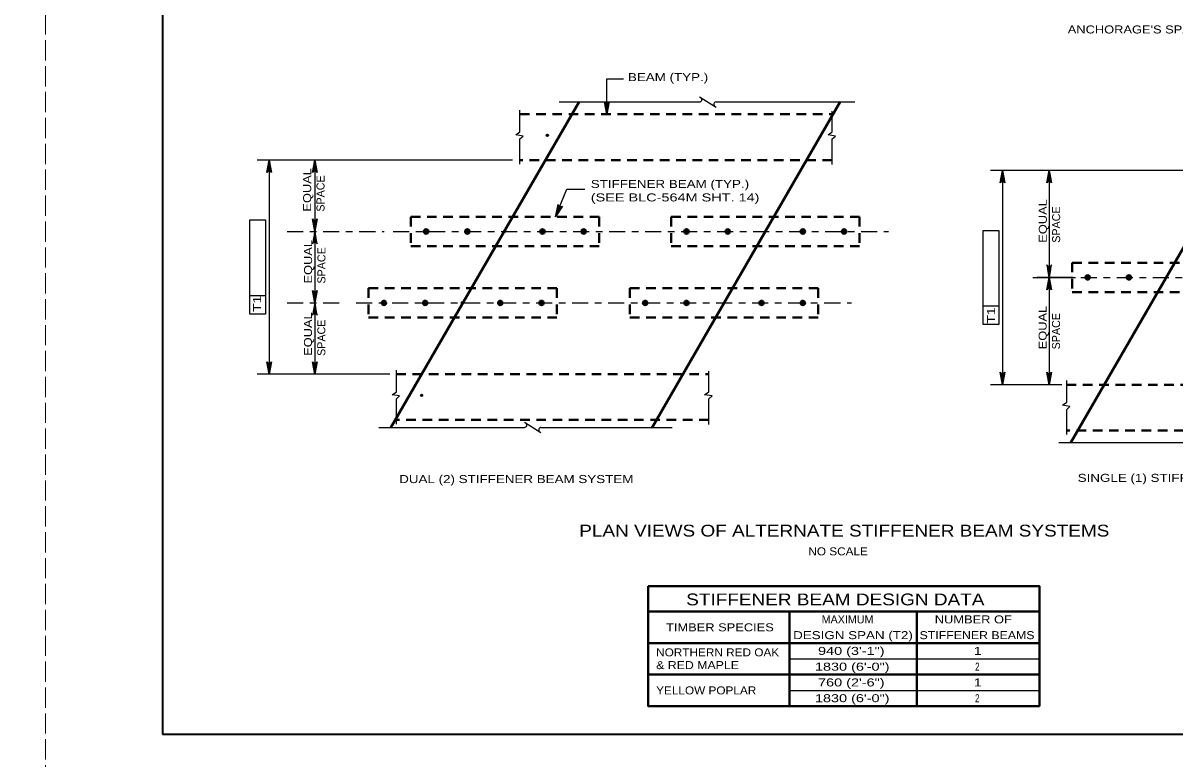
# Model space of a CAD drawing. Extents: x -11 to 79, y -154 to 0.
# Drawn here: x 33.66 to 50.93, y -87.62 to -76.59 of the extents above; entities that cross this region are included whole.
import ezdxf
from ezdxf.enums import TextEntityAlignment as Align

# ---------------------------------------------------------------- set-up
doc = ezdxf.new("R2010")
doc.units = 0
doc.header["$LTSCALE"] = 0.048
doc.header["$PDMODE"] = 32
doc.header["$PDSIZE"] = 0.024
for name, pattern in [('DOT_DASHED', [7.7, 5, -1.2, 0.3, -1.2]), ('LONG_DASHED', [7.5, 6, -1.5]), ('MEDIUM_DASHED', [4.5, 3, -1.5])]:
    doc.linetypes.add(name, pattern=pattern)
for name, color, linetype, lineweight in [('1', 7, 'Continuous', 25), ('10', 7, 'Continuous', 40), ('2', 7, 'Continuous', 35), ('3', 7, 'Continuous', 25), ('4', 7, 'Continuous', 25), ('63', 7, 'LONG_DASHED', 13), ('8', 7, 'Continuous', 35)]:
    doc.layers.add(name, color=color, linetype=linetype, lineweight=lineweight)

msp = doc.modelspace()

# ---------------------------------------------------------------- hatches: boundary and pattern name
at = {"layer": '4'}
for points in [[(42.4125, -77.9585), (42.41367, -77.95375), (42.41125, -77.95375)], [(48.3255, -78.92025), (48.3655, -78.92025), (48.3455, -78.80025)], [(49.02583, -78.92025), (49.06583, -78.92025), (49.04583, -78.80025)], [(41.64325, -79.49425), (41.64617, -79.49033), (41.64392, -79.48942)], [(49.02583, -80.28158), (49.06583, -80.28158), (49.04583, -80.40158)], [(49.02583, -80.52158), (49.06583, -80.52158), (49.04583, -80.40158)], [(38.01517, -80.6655), (38.05458, -80.6655), (38.03492, -80.78358)], [(38.01775, -80.90175), (38.05708, -80.90175), (38.03742, -80.78358)], [(37.33175, -81.73367), (37.37175, -81.73367), (37.35175, -81.85367)], [(38.01775, -81.73558), (38.05708, -81.73558), (38.03742, -81.85367)], [(48.3255, -81.8905), (48.3655, -81.8905), (48.3455, -82.0105)], [(49.02583, -81.88283), (49.06583, -81.88283), (49.04583, -82.00283)]]:
    msp.add_hatch(color=256, dxfattribs=at).paths.add_polyline_path(points)

# ---------------------------------------------------------------- linework, layer by layer
at = {"layer": '1', "lineweight": 35}
msp.add_lwpolyline([(35.75, -87.25), (67.25, -87.25), (67.25, -66.75), (35.75, -66.75)], close=True, dxfattribs=at)
at = {"layer": '10'}
for p, q in [((43.03117, -85.41033), (48.89708, -85.41033)), ((45.15033, -85.41033), (45.15033, -86.82758)), ((47.06133, -85.41033), (47.06133, -86.82758)), ((43.03117, -85.88275), (48.89708, -85.88275)), ((43.03117, -86.35517), (48.89708, -86.35517))]:
    msp.add_line(p, q, dxfattribs=at)
at = {"layer": '10', "lineweight": 25}
for p, q in [((45.15033, -86.119), (48.89708, -86.119)), ((45.15033, -86.59142), (48.89708, -86.59142))]:
    msp.add_line(p, q, dxfattribs=at)
at = {"layer": '10'}
for points in [[(43.03117, -85.02875), (43.03117, -86.82758), (48.89708, -86.82758)], [(43.03117, -85.02875), (48.89708, -85.02875), (48.89708, -86.82758)]]:
    msp.add_lwpolyline(points, dxfattribs=at)
at = {"layer": '2', "lineweight": 53}
for p, q in [((41.99692, -77.77325), (39.17725, -82.65125)), ((45.91025, -77.77325), (43.09058, -82.65125)), ((52.23908, -77.90983), (49.36767, -82.87733))]:
    msp.add_line(p, q, dxfattribs=at)
at = {"layer": '3'}
for p, q in [((43.80425, -77.69583), (44.05058, -77.85067)), ((41.7, -77.77325), (43.80142, -77.77325)), ((44.05008, -77.77325), (46.133, -77.77325)), ((45.792, -78.21992), (45.792, -77.91092)), ((45.73042, -78.2675), (45.792, -78.21992)), ((41.15783, -78.28442), (41.0475, -78.2675)), ((41.10908, -78.32817), (41.15783, -78.28442)), ((41.10908, -78.70508), (41.10908, -78.32817)), ((45.84075, -78.28442), (45.73042, -78.2675)), ((45.792, -78.32817), (45.84075, -78.28442)), ((45.792, -78.71258), (45.792, -78.32817)), ((43.94125, -82.11517), (43.94125, -81.80617)), ((49.30625, -82.272), (49.30625, -81.948)), ((43.87967, -82.16267), (43.94125, -82.11517)), ((43.99, -82.17967), (43.87967, -82.16267)), ((43.94125, -82.22342), (43.99, -82.17967)), ((43.94125, -82.60783), (43.94125, -82.22342)), ((49.24467, -82.3195), (49.30625, -82.272)), ((49.355, -82.3365), (49.24467, -82.3195)), ((49.30625, -82.38025), (49.355, -82.3365)), ((49.30625, -82.75717), (49.30625, -82.38025)), ((38.9975, -82.65125), (41.17675, -82.65125)), ((41.17958, -82.57383), (41.42592, -82.72867)), ((41.42542, -82.65125), (43.39142, -82.65125)), ((49.18792, -82.87733), (51.36725, -82.87733))]:
    msp.add_line(p, q, dxfattribs=at)
at = {"layer": '3', "linetype": 'MEDIUM_DASHED', "lineweight": 40}
for p, q in [((41.10908, -77.9585), (45.792, -77.9585)), ((45.792, -78.64342), (41.10908, -78.64342)), ((39.47383, -79.49425), (39.47383, -79.93517)), ((39.47383, -79.93517), (42.29667, -79.93517)), ((49.39083, -80.18225), (52.21367, -80.18225)), ((49.39083, -80.18225), (49.39083, -80.62325)), ((38.84142, -80.56433), (41.66425, -80.56433)), ((38.84142, -80.56433), (38.84142, -81.00525)), ((41.66425, -80.56433), (41.66425, -81.00525)), ((42.75808, -80.56433), (45.58092, -80.56433)), ((42.75808, -80.56433), (42.75808, -81.00525)), ((45.58092, -80.56433), (45.58092, -81.00525)), ((49.39083, -80.62325), (52.21367, -80.62325)), ((38.84142, -81.00525), (41.66425, -81.00525)), ((42.75808, -81.00525), (45.58092, -81.00525)), ((39.25833, -81.85367), (43.94125, -81.85367)), ((49.30625, -82.0105), (53.98917, -82.0105)), ((43.94125, -82.53867), (39.25833, -82.53867)), ((53.98917, -82.6955), (49.30625, -82.6955))]:
    msp.add_line(p, q, dxfattribs=at)
at = {"layer": '3'}
for points in [[(41.0475, -78.2675), (41.10908, -78.21992), (41.10908, -77.896)], [(39.25833, -82.60033), (39.25833, -82.22342), (39.30708, -82.17967), (39.19675, -82.16267), (39.25833, -82.11517), (39.25833, -81.79117)]]:
    msp.add_lwpolyline(points, dxfattribs=at)
at = {"layer": '3', "linetype": 'MEDIUM_DASHED', "lineweight": 40}
for points in [[(39.47383, -79.49425), (42.29667, -79.49425), (42.29667, -79.93517)], [(43.37733, -79.49425), (43.37733, -79.93517), (46.20017, -79.93517)], [(43.37733, -79.49425), (46.20017, -79.49425), (46.20017, -79.93517)]]:
    msp.add_lwpolyline(points, dxfattribs=at)
at = {"layer": '3', "lineweight": 40}
for centre, radius in [((39.70412, -79.71471), 0.03333), ((39.70412, -79.71471), 0.025), ((39.70412, -79.71471), 0.01667), ((39.70412, -79.71471), 0.00833), ((40.32223, -79.71471), 0.03333), ((40.32223, -79.71471), 0.025), ((40.32223, -79.71471), 0.01667), ((40.32223, -79.71471), 0.00833), ((41.44821, -79.71471), 0.03333), ((41.44821, -79.71471), 0.025), ((41.44821, -79.71471), 0.01667), ((41.44821, -79.71471), 0.00833), ((42.06632, -79.71471), 0.03333), ((42.06632, -79.71471), 0.025), ((42.06632, -79.71471), 0.01667), ((42.06632, -79.71471), 0.00833), ((43.60759, -79.71471), 0.03333), ((43.60759, -79.71471), 0.025), ((43.60759, -79.71471), 0.01667), ((43.60759, -79.71471), 0.00833), ((44.2257, -79.71471), 0.03333), ((44.2257, -79.71471), 0.025), ((44.2257, -79.71471), 0.01667), ((44.2257, -79.71471), 0.00833), ((45.35168, -79.71471), 0.03333), ((45.35168, -79.71471), 0.025), ((45.35168, -79.71471), 0.01667), ((45.35168, -79.71471), 0.00833), ((45.96979, -79.71471), 0.03333), ((45.96979, -79.71471), 0.025), ((45.96979, -79.71471), 0.01667), ((45.96979, -79.71471), 0.00833), ((49.62109, -80.40274), 0.03333), ((49.62109, -80.40274), 0.02953), ((49.62109, -80.40274), 0.025), ((49.62109, -80.40274), 0.01667), ((49.62109, -80.40274), 0.00833), ((50.2392, -80.40274), 0.03333), ((50.2392, -80.40274), 0.02953), ((50.2392, -80.40274), 0.025), ((50.2392, -80.40274), 0.01667), ((50.2392, -80.40274), 0.00833), ((39.07174, -80.78479), 0.03333), ((39.07174, -80.78479), 0.025), ((39.07174, -80.78479), 0.01667), ((39.07174, -80.78479), 0.00833), ((39.68985, -80.78479), 0.03333), ((39.68985, -80.78479), 0.025), ((39.68985, -80.78479), 0.01667), ((39.68985, -80.78479), 0.00833), ((40.81583, -80.78479), 0.03333), ((40.81583, -80.78479), 0.025), ((40.81583, -80.78479), 0.01667), ((40.81583, -80.78479), 0.00833), ((41.43394, -80.78479), 0.03333), ((41.43394, -80.78479), 0.025), ((41.43394, -80.78479), 0.01667), ((41.43394, -80.78479), 0.00833), ((42.98837, -80.78479), 0.03333), ((42.98837, -80.78479), 0.025), ((42.98837, -80.78479), 0.01667), ((42.98837, -80.78479), 0.00833), ((43.60648, -80.78479), 0.03333), ((43.60648, -80.78479), 0.025), ((43.60648, -80.78479), 0.01667), ((43.60648, -80.78479), 0.00833), ((44.73246, -80.78479), 0.03333), ((44.73246, -80.78479), 0.025), ((44.73246, -80.78479), 0.01667), ((44.73246, -80.78479), 0.00833), ((45.35057, -80.78479), 0.03333), ((45.35057, -80.78479), 0.025), ((45.35057, -80.78479), 0.01667), ((45.35057, -80.78479), 0.00833)]:
    msp.add_circle(centre, radius, dxfattribs=at)
at = {"layer": '3'}
for centre in [(39.70412, -79.71471), (40.32223, -79.71471), (41.44821, -79.71471), (42.06632, -79.71471), (43.60759, -79.71471), (44.2257, -79.71471), (45.35168, -79.71471), (45.96979, -79.71471), (39.07174, -80.78479), (39.68985, -80.78479), (40.81583, -80.78479), (41.43394, -80.78479), (42.98837, -80.78479), (43.60648, -80.78479), (44.73246, -80.78479), (45.35057, -80.78479)]:
    msp.add_circle(centre, 0.02953, dxfattribs=at)
for centre, start, end in [((43.80141, -77.73685), 270, 60), ((44.05344, -77.80943), 95.32859, 237.86724), ((41.17673, -82.6149), 270, 60), ((41.42876, -82.68748), 95.32859, 237.86724)]:
    msp.add_arc(centre, 0.03637, start, end, dxfattribs=at)
for p in [(40.88183, -79.7135), (40.24942, -80.78358)]:
    msp.add_point(p, dxfattribs=at)
at = {"layer": '4'}
for p, q in [((42.4125, -77.9585), (42.4125, -77.425)), ((42.4125, -77.425), (42.66258, -77.425)), ((38.7015, -78.64342), (37.17175, -78.64342)), ((37.35175, -78.64342), (37.35175, -81.85367)), ((40.99658, -78.64342), (37.58917, -78.64342)), ((38.54858, -78.64342), (37.94633, -78.64342)), ((38.03492, -78.64342), (38.03492, -79.7135)), ((49.40525, -78.80025), (48.1655, -78.80025)), ((48.3455, -78.80025), (48.3455, -82.0105)), ((51.42308, -78.80025), (48.86583, -78.80025)), ((49.04583, -78.80025), (49.04583, -80.40158)), ((41.64325, -79.49425), (41.81592, -79.08183)), ((41.81592, -79.08183), (42.08233, -79.08183)), ((37.06025, -79.54167), (37.2965, -79.54167)), ((37.06025, -80.95367), (37.06025, -79.54167)), ((37.2965, -79.54167), (37.2965, -80.95367)), ((38.03492, -79.7135), (38.03492, -80.6655)), ((48.054, -79.6985), (48.29017, -79.6985)), ((48.054, -80.81167), (48.054, -79.6985)), ((48.29017, -79.6985), (48.29017, -81.1105)), ((48.80108, -80.40158), (49.44058, -80.40158)), ((49.40525, -80.40158), (48.86583, -80.40158)), ((49.04583, -80.40158), (49.04583, -82.0105)), ((37.2965, -80.67808), (37.06025, -80.67808)), ((48.054, -81.1105), (48.054, -80.81167)), ((37.2965, -80.95367), (37.06025, -80.95367)), ((38.03742, -80.90175), (38.03742, -81.85367)), ((48.29017, -80.83492), (48.054, -80.83492)), ((48.29017, -81.1105), (48.054, -81.1105)), ((39.15958, -81.85367), (37.17175, -81.85367)), ((38.29675, -81.85367), (37.96175, -81.85367)), ((49.23325, -82.0105), (48.1655, -82.0105))]:
    msp.add_line(p, q, dxfattribs=at)
at = {"layer": '4', "linetype": 'DOT_DASHED'}
for p, q in [((37.623, -79.7135), (39.075, -79.7135)), ((39.20792, -79.7135), (46.63367, -79.7135)), ((49.51892, -80.40275), (56.81008, -80.40275)), ((37.623, -80.78358), (38.49492, -80.78358)), ((38.65342, -80.78483), (46.07917, -80.78483))]:
    msp.add_line(p, q, dxfattribs=at)
at = {"layer": '4'}
for points in [[(42.4125, -77.9585), (42.37758, -77.77208), (42.3875, -77.78642), (42.4, -77.79383), (42.4125, -77.796), (42.425, -77.79383), (42.4375, -77.78642), (42.44742, -77.77208), (42.4125, -77.9585), (42.4375, -77.78642), (42.425, -77.79383), (42.4125, -77.9585), (42.4125, -77.796), (42.4, -77.79383), (42.4125, -77.9585), (42.3875, -77.78642)], [(37.35175, -78.64342), (37.38667, -78.82983), (37.37675, -78.8155), (37.36425, -78.80808), (37.35175, -78.80592), (37.33925, -78.80808), (37.32675, -78.8155), (37.31683, -78.82983), (37.35175, -78.64342), (37.32675, -78.8155), (37.33925, -78.80808), (37.35175, -78.64342), (37.35175, -78.80592), (37.36425, -78.80808), (37.35175, -78.64342), (37.37675, -78.8155)], [(38.03492, -78.64342), (38.06983, -78.82983), (38.05992, -78.8155), (38.04742, -78.80808), (38.03492, -78.80592), (38.02242, -78.80808), (38.00992, -78.8155), (38, -78.82983), (38.03492, -78.64342), (38.00992, -78.8155), (38.02242, -78.80808), (38.03492, -78.64342), (38.03492, -78.80592), (38.04742, -78.80808), (38.03492, -78.64342), (38.05992, -78.8155)], [(48.3455, -78.80025), (48.38042, -78.98667), (48.3705, -78.97233), (48.358, -78.96492), (48.3455, -78.96275), (48.333, -78.96492), (48.3205, -78.97233), (48.31058, -78.98667), (48.3455, -78.80025), (48.3205, -78.97233), (48.333, -78.96492), (48.3455, -78.80025), (48.3455, -78.96275), (48.358, -78.96492), (48.3455, -78.80025), (48.3705, -78.97233)], [(49.04583, -78.80025), (49.08075, -78.98667), (49.07083, -78.97233), (49.05833, -78.96492), (49.04583, -78.96275), (49.03333, -78.96492), (49.02083, -78.97233), (49.01092, -78.98667), (49.04583, -78.80025), (49.02083, -78.97233), (49.03333, -78.96492), (49.04583, -78.80025), (49.04583, -78.96275), (49.05833, -78.96492), (49.04583, -78.80025), (49.07083, -78.97233)], [(41.64325, -79.49425), (41.683, -79.30883), (41.68667, -79.32592), (41.69533, -79.33758), (41.706, -79.34433), (41.71833, -79.34717), (41.73275, -79.34517), (41.7475, -79.33583), (41.64325, -79.49425), (41.73275, -79.34517), (41.71833, -79.34717), (41.64325, -79.49425), (41.706, -79.34433), (41.69533, -79.33758), (41.64325, -79.49425), (41.68667, -79.32592)], [(38.03492, -79.7135), (38, -79.52708), (38.00992, -79.54142), (38.02242, -79.54883), (38.03492, -79.551), (38.04742, -79.54883), (38.05992, -79.54142), (38.06983, -79.52708), (38.03492, -79.7135), (38.05992, -79.54142), (38.04742, -79.54883), (38.03492, -79.7135), (38.03492, -79.551), (38.02242, -79.54883), (38.03492, -79.7135), (38.00992, -79.54142)], [(38.03492, -79.7135), (38, -79.89992), (38.00992, -79.88558), (38.02242, -79.87817), (38.03492, -79.876), (38.04742, -79.87817), (38.05992, -79.88558), (38.06983, -79.89992), (38.03492, -79.7135), (38.05992, -79.88558), (38.04742, -79.87817), (38.03492, -79.7135), (38.03492, -79.876), (38.02242, -79.87817), (38.03492, -79.7135), (38.00992, -79.88558)], [(49.04583, -80.40158), (49.08075, -80.21517), (49.07083, -80.2295), (49.05833, -80.23692), (49.04583, -80.23908), (49.03333, -80.23692), (49.02083, -80.2295), (49.01092, -80.21517), (49.04583, -80.40158), (49.02083, -80.2295), (49.03333, -80.23692), (49.04583, -80.40158), (49.04583, -80.23908), (49.05833, -80.23692), (49.04583, -80.40158), (49.07083, -80.2295)], [(49.04583, -80.40158), (49.08075, -80.588), (49.07083, -80.57367), (49.05833, -80.56625), (49.04583, -80.56408), (49.03333, -80.56625), (49.02083, -80.57367), (49.01092, -80.588), (49.04583, -80.40158), (49.02083, -80.57367), (49.03333, -80.56625), (49.04583, -80.40158), (49.04583, -80.56408), (49.05833, -80.56625), (49.04583, -80.40158), (49.07083, -80.57367)], [(38.03742, -80.78358), (38.0025, -80.59717), (38.01242, -80.6115), (38.02492, -80.61892), (38.03742, -80.62108), (38.04992, -80.61892), (38.06242, -80.6115), (38.07233, -80.59717), (38.03742, -80.78358), (38.06242, -80.6115), (38.04992, -80.61892), (38.03742, -80.78358), (38.03742, -80.62108), (38.02492, -80.61892), (38.03742, -80.78358), (38.01242, -80.6115)], [(38.03742, -80.78358), (38.0025, -80.97), (38.01242, -80.95567), (38.02492, -80.94825), (38.03742, -80.94608), (38.04992, -80.94825), (38.06242, -80.95567), (38.07233, -80.97), (38.03742, -80.78358), (38.06242, -80.95567), (38.04992, -80.94825), (38.03742, -80.78358), (38.03742, -80.94608), (38.02492, -80.94825), (38.03742, -80.78358), (38.01242, -80.95567)], [(37.35175, -81.85367), (37.31683, -81.66725), (37.32675, -81.68158), (37.33925, -81.689), (37.35175, -81.69117), (37.36425, -81.689), (37.37675, -81.68158), (37.38667, -81.66725), (37.35175, -81.85367), (37.37675, -81.68158), (37.36425, -81.689), (37.35175, -81.85367), (37.35175, -81.69117), (37.33925, -81.689), (37.35175, -81.85367), (37.32675, -81.68158)], [(38.03742, -81.85367), (38.0025, -81.66725), (38.01242, -81.68158), (38.02492, -81.689), (38.03742, -81.69117), (38.04992, -81.689), (38.06242, -81.68158), (38.07233, -81.66725), (38.03742, -81.85367), (38.06242, -81.68158), (38.04992, -81.689), (38.03742, -81.85367), (38.03742, -81.69117), (38.02492, -81.689), (38.03742, -81.85367), (38.01242, -81.68158)], [(48.3455, -82.0105), (48.31058, -81.82408), (48.3205, -81.83842), (48.333, -81.84583), (48.3455, -81.848), (48.358, -81.84583), (48.3705, -81.83842), (48.38042, -81.82408), (48.3455, -82.0105), (48.3705, -81.83842), (48.358, -81.84583), (48.3455, -82.0105), (48.3455, -81.848), (48.333, -81.84583), (48.3455, -82.0105), (48.3205, -81.83842)], [(49.04583, -82.0105), (49.01092, -81.82408), (49.02083, -81.83842), (49.03333, -81.84583), (49.04583, -81.848), (49.05833, -81.84583), (49.07083, -81.83842), (49.08075, -81.82408), (49.04583, -82.0105), (49.07083, -81.83842), (49.05833, -81.84583), (49.04583, -82.0105), (49.04583, -81.848), (49.03333, -81.84583), (49.04583, -82.0105), (49.02083, -81.83842)]]:
    msp.add_lwpolyline(points, dxfattribs=at)
for points in [[(42.4125, -77.9585), (42.41367, -77.95375), (42.41125, -77.95375)], [(48.3255, -78.92025), (48.3655, -78.92025), (48.3455, -78.80025)], [(49.02583, -78.92025), (49.06583, -78.92025), (49.04583, -78.80025)], [(41.64325, -79.49425), (41.64617, -79.49033), (41.64392, -79.48942)], [(49.02583, -80.28158), (49.06583, -80.28158), (49.04583, -80.40158)], [(49.02583, -80.52158), (49.06583, -80.52158), (49.04583, -80.40158)], [(38.01517, -80.6655), (38.05458, -80.6655), (38.03492, -80.78358)], [(38.01775, -80.90175), (38.05708, -80.90175), (38.03742, -80.78358)], [(37.33175, -81.73367), (37.37175, -81.73367), (37.35175, -81.85367)], [(38.01775, -81.73558), (38.05708, -81.73558), (38.03742, -81.85367)], [(48.3255, -81.8905), (48.3655, -81.8905), (48.3455, -82.0105)], [(49.02583, -81.88283), (49.06583, -81.88283), (49.04583, -82.00283)]]:
    msp.add_lwpolyline(points, close=True, dxfattribs=at)
at = {"layer": '63'}
for points in [[(0, -88), (34, -88), (34, -66), (0, -66)], [(34, -88), (68, -88), (68, -66), (34, -66)]]:
    msp.add_lwpolyline(points, close=True, dxfattribs=at)
at = {"layer": '8'}
for p in [(41.52017, -78.27433), (41.52083, -78.27317), (40.88183, -79.7135), (40.24942, -80.78358), (39.63825, -82.1695)]:
    msp.add_point(p, dxfattribs=at)

# ---------------------------------------------------------------- texts
at = {"layer": '4'}
for s, width, p in [("ANCHORAGE'S SPACING MAY BE NECESSARY.", 1.2, (49.32283, -76.74683)), ('BEAM (TYP.)', 1.25, (42.72942, -77.46108)), ('STIFFENER BEAM (TYP.)', 1.25, (42.17267, -79.06233)), ('(SEE BLC-564M SHT. 14)', 1.35, (42.17267, -79.26417)), ('NO SCALE', 1.1, (45.43392, -84.568)), ('NORTHERN RED OAK', 1.1, (43.15267, -86.08167)), ('& RED MAPLE', 1.15, (43.15267, -86.27283)), ('YELLOW POPLAR', 1.1, (43.15267, -86.65142))]:
    msp.add_text(s, height=0.12, dxfattribs=dict(at, width=width)).set_placement(p)
at = {"layer": '4', "width": 1.3}
for p in [(37.23033, -80.79954), (48.233, -80.97437)]:
    msp.add_text('T1', height=0.12, rotation=90, dxfattribs=at).set_placement(p, align=Align.CENTER)
at = {"layer": '4'}
for s, height, width, p in [('DUAL (2) STIFFENER BEAM SYSTEM', 0.12, 1.25, (41.05604, -83.485)), ('SINGLE (1) STIFFENER BEAM SYSTEM', 0.12, 1.25, (51.32725, -83.46667)), ('PLAN VIEWS OF ALTERNATE STIFFENER BEAM SYSTEMS', 0.1772, 1.2, (45.97279, -84.28592)), ('STIFFENER BEAM DESIGN DATA', 0.1772, 1.2, (45.83833, -85.317)), ('NUMBER OF ', 0.12, 1.2, (47.93354, -85.5875)), ('TIMBER SPECIES', 0.12, 1.2, (44.10846, -85.70658)), ('DESIGN SPAN (T2)', 0.12, 1.25, (46.10337, -85.82367)), ('STIFFENER BEAMS', 0.12, 1.15, (47.9625, -85.82367)), ('940 (3\'-1")', 0.12, 1.35, (46.07771, -86.05992)), ('1', 0.12, 1.3, (47.97187, -86.05992)), ('1830 (6\'-0")', 0.12, 1.35, (46.09158, -86.29608)), ('2', 0.12, 0.75, (47.96688, -86.29608)), ('760 (2\'-6")', 0.12, 1.35, (46.07771, -86.53233)), ('1', 0.12, 1.3, (47.97187, -86.53233)), ('1830 (6\'-0")', 0.12, 1.35, (46.09158, -86.76858)), ('2', 0.12, 0.75, (47.96688, -86.76858))]:
    msp.add_text(s, height=height, dxfattribs=dict(at, width=width)).set_placement(p, align=Align.CENTER)
msp.add_text('MAXIMUM', height=0.12, dxfattribs=at).set_placement((46.02158, -85.5875), align=Align.CENTER)
at = {"layer": '8', "width": 1.2}
for p in [(37.98083, -79.41708), (49.0085, -79.88342), (37.99442, -80.49442), (37.99283, -81.57867), (49.006, -81.48067)]:
    msp.add_text('EQUAL ', height=0.12, rotation=89.971, dxfattribs=at).set_placement(p)
at = {"layer": '8'}
for p in [(38.18083, -79.41717), (49.2085, -79.8835), (38.19442, -80.4945), (49.206, -81.48075), (38.19283, -81.57875)]:
    msp.add_text('SPACE', height=0.12, rotation=89.971, dxfattribs=at).set_placement(p)

doc.saveas('drawing.dxf')
